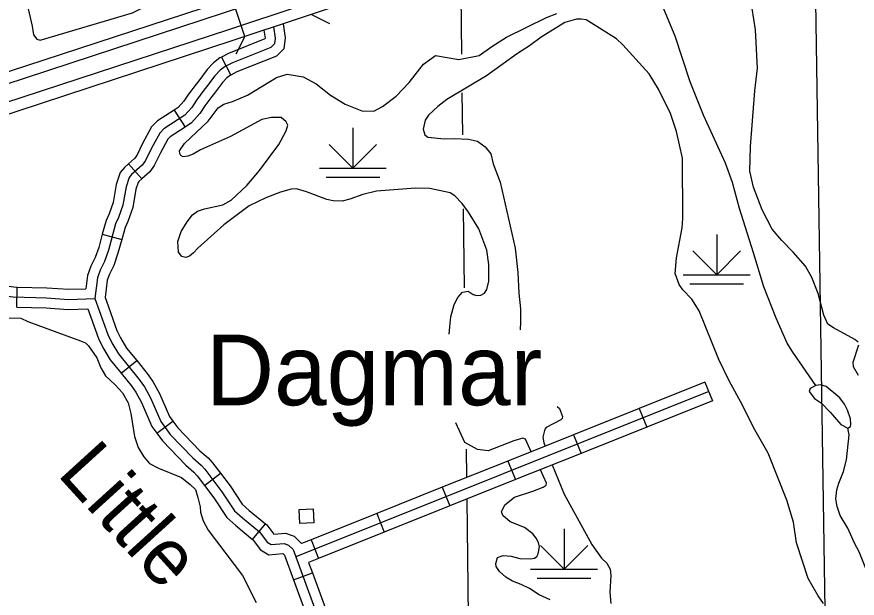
# Model space of a CAD drawing. Extents: x 1084508 to 1142749, y 1057638 to 1093403.
# Drawn here: x 1091747 to 1093716, y 1070432 to 1071794 of the extents above; entities that cross this region are included whole.
import ezdxf

# ---------------------------------------------------------------- set-up
doc = ezdxf.new("R2010")
doc.units = 0
for name, color, linetype in [('Level 19', 7, 'Continuous'), ('Level 25', 7, 'Continuous'), ('Level 32', 7, 'Continuous'), ('Level 35', 7, 'Continuous'), ('Level 39', 7, 'Continuous'), ('Level 44', 7, 'Continuous'), ('Level 47', 7, 'Continuous'), ('Level 5', 7, 'Continuous'), ('Level 56', 7, 'Continuous'), ('Level 7', 7, 'Continuous')]:
    doc.layers.add(name, color=color, linetype=linetype)

msp = doc.modelspace()

# ---------------------------------------------------------------- linework, layer by layer
at = {"layer": 'Level 19'}
for points in [[(1086828.8, 1069564.8), (1086958.3, 1069597.9), (1087305.2, 1069683.8), (1087445.9, 1069710.7), (1087821, 1069773.1), (1088253.5, 1069840.9), (1088436.6, 1069876.1), (1088626, 1069927.2), (1088752.5, 1069969), (1088851.8, 1070006.5), (1088959.6, 1070052.9), (1089051.3, 1070099.1), (1089145.7, 1070149.3), (1089264, 1070224), (1089345.2, 1070271.9), (1090501.3, 1071000.2), (1091111.9, 1071388.7), (1091276, 1071487.3), (1091344.3, 1071524.2), (1091404.7, 1071552.9), (1091443.8, 1071569.2), (1091605.2, 1071625.7), (1092224.5, 1071828.5), (1094022, 1072425.4)], [(1094030.9, 1072400.2), (1092232.9, 1071803.1), (1091613.8, 1071600.4), (1091453.4, 1071544.3), (1091415.6, 1071528.5), (1091356.3, 1071500.4), (1091289.2, 1071464.1), (1091126, 1071366), (1090515.6, 1070977.7), (1089359.1, 1070249.2), (1089277.9, 1070201.2), (1089159.1, 1070126.2), (1089063.6, 1070075.4), (1088970.9, 1070028.7), (1088861.8, 1069981.8), (1088761.4, 1069943.9), (1088633.7, 1069901.6), (1088442.6, 1069850.1), (1088258.1, 1069814.7), (1087825.3, 1069746.7), (1087450.6, 1069684.4), (1087310.9, 1069657.7), (1086964.9, 1069572), (1086833.1, 1069538.3)], [(1094044.5, 1072361.7), (1092245.7, 1071764.4), (1091626.8, 1071561.8), (1091468, 1071506.2), (1091432.2, 1071491.3), (1091374.8, 1071464), (1091309.5, 1071428.7), (1091147.4, 1071331.3), (1090537.4, 1070943.2), (1089380.4, 1070214.3), (1089299.2, 1070166.4), (1089179.6, 1070090.9), (1089082.3, 1070039.1), (1088988.1, 1069991.7), (1088877.1, 1069943.9), (1088775, 1069905.4), (1088645.4, 1069862.5), (1088451.8, 1069810.3), (1088265.1, 1069774.4), (1087831.8, 1069706.5), (1087457.7, 1069644.3), (1087319.6, 1069617.8), (1086974.8, 1069532.5), (1086844.1, 1069499)], [(1086853, 1069473.8), (1086981.3, 1069506.6), (1087325.3, 1069591.8), (1087462.4, 1069618), (1087836, 1069680.1), (1088269.7, 1069748.2), (1088457.8, 1069784.3), (1088653.1, 1069837), (1088783.9, 1069880.3), (1088887.1, 1069919.2), (1088999.4, 1069967.5), (1089094.6, 1070015.5), (1089193, 1070067.8), (1089313.1, 1070143.6), (1089394.3, 1070191.5), (1090551.7, 1070920.7), (1091161.5, 1071308.6), (1091322.7, 1071405.5), (1091386.9, 1071440.2), (1091443.1, 1071466.9), (1091477.6, 1071481.3), (1091635.4, 1071536.5), (1092254, 1071739), (1094053.4, 1072336.6)]]:
    msp.add_lwpolyline(points, dxfattribs=at)
at = {"layer": 'Level 32'}
for p, q in [((1092227.1, 1071699.4), (1092248.6, 1071657.5)), ((1092116.1, 1071575.2), (1092141.8, 1071535.7)), ((1092009.2, 1071449.5), (1092040.2, 1071414.1)), ((1091947.6, 1071284.5), (1091993, 1071272)), ((1091747.2, 1071113.6), (1091748.4, 1071160.7)), ((1091991.6, 1070958.9), (1092028.1, 1070988.7)), ((1093359.8, 1070937.8), (1093377.3, 1070894.1)), ((1093205.9, 1070876.2), (1093223.4, 1070832.5)), ((1092075.1, 1070818.3), (1092112.9, 1070846.3)), ((1093052, 1070814.6), (1093069.5, 1070770.9)), ((1092898.2, 1070753), (1092915.7, 1070709.3)), ((1092186.7, 1070696), (1092224.2, 1070724.4)), ((1092744.3, 1070691.4), (1092761.8, 1070647.7)), ((1092590.5, 1070629.8), (1092608, 1070586.1)), ((1092299.8, 1070569.4), (1092329.8, 1070605.6)), ((1092436.6, 1070568.2), (1092454.1, 1070524.5)), ((1092395.8, 1070474.6), (1092440, 1070490.8))]:
    msp.add_line(p, q, dxfattribs=at)
for points in [[(1092371.2, 1071777.9), (1092376.4, 1071744.7), (1092373.3, 1071719.3), (1092355.6, 1071702.1), (1092262.8, 1071664.8), (1092248.6, 1071657.5)], [(1092348.6, 1071770.4), (1092352.6, 1071744.3), (1092351, 1071730.4), (1092342.5, 1071722.2), (1092253, 1071686.3), (1092235.8, 1071677.4), (1092223.9, 1071668.6), (1092211.5, 1071655.4), (1092192, 1071629.6)], [(1092325.9, 1071762.9), (1092328.9, 1071743.9), (1092328.6, 1071742), (1092243.2, 1071707.7), (1092227.1, 1071699.4)], [(1092227.1, 1071699.4), (1092223.3, 1071697.5), (1092208.2, 1071686.3), (1092193.4, 1071670.6), (1092173.4, 1071644), (1092167.2, 1071636.3), (1092149.2, 1071612.5), (1092138.4, 1071596.1), (1092125.4, 1071581.2), (1092116.1, 1071575.2)], [(1092248.6, 1071657.5), (1092248.2, 1071657.4), (1092239.6, 1071651), (1092229.5, 1071640.2), (1092210.6, 1071615.1), (1092204.3, 1071607.3), (1092187.7, 1071585.3), (1092176, 1071567.5), (1092156.5, 1071545.3), (1092141.8, 1071535.7)], [(1092192, 1071629.6), (1092185.8, 1071621.8), (1092168.4, 1071598.9), (1092157.2, 1071581.8), (1092141, 1071563.3), (1092092, 1071531.5), (1092082.1, 1071521.6), (1092062.8, 1071486.3), (1092048.5, 1071457.1), (1092041.1, 1071446.1), (1092016.2, 1071424.4), (1092010.3, 1071417.2), (1092003.3, 1071395.6), (1091995.8, 1071352.8), (1091985.7, 1071323.5), (1091978.7, 1071308.8), (1091961.7, 1071246.8), (1091953, 1071220.6), (1091942.5, 1071200.4), (1091936, 1071182.2), (1091930.3, 1071133.6)], [(1092116.1, 1071575.2), (1092077.2, 1071549.9), (1092063.1, 1071536), (1092041.8, 1071497.1), (1092028.1, 1071468.9), (1092023.3, 1071461.8), (1092009.2, 1071449.5)], [(1092141.8, 1071535.7), (1092106.9, 1071513), (1092101.1, 1071507.3), (1092083.7, 1071475.5), (1092069, 1071445.3), (1092058.9, 1071430.4), (1092040.2, 1071414.1)], [(1092009.2, 1071449.5), (1091999.4, 1071440.9), (1091989.3, 1071428.8), (1091980.3, 1071401.2), (1091972.9, 1071358.7), (1091963.8, 1071332.4), (1091956.6, 1071317), (1091947.6, 1071284.5)], [(1092040.2, 1071414.1), (1092033.1, 1071407.9), (1092031.2, 1071405.6), (1092026.2, 1071389.9), (1092018.7, 1071346.9), (1092007.5, 1071314.6), (1092000.9, 1071300.6), (1091993, 1071272)], [(1091947.6, 1071284.5), (1091939.1, 1071253.6), (1091931.2, 1071229.8), (1091920.8, 1071209.9), (1091912.9, 1071187.6), (1091909.3, 1071156.5)], [(1091993, 1071272), (1091984.2, 1071239.9), (1091974.7, 1071211.4), (1091964.1, 1071191), (1091959, 1071176.8), (1091954.3, 1071136.3), (1091957.3, 1071127.9)], [(1091235.4, 1071212.6), (1091275.6, 1071150.7), (1091294.6, 1071116.2), (1091309.1, 1071099.4), (1091324.3, 1071086.5), (1091336.7, 1071082.9), (1091349.8, 1071084.1), (1091360.3, 1071088.3), (1091371.6, 1071095.9), (1091394.6, 1071117.9), (1091427, 1071139.6), (1091440.8, 1071146.1), (1091459.1, 1071152.2), (1091492.2, 1071156), (1091521.7, 1071154), (1091551.7, 1071149.2), (1091587.5, 1071147.2), (1091659, 1071147.1), (1091738.6, 1071137.4), (1091816.8, 1071135.4), (1091868.3, 1071131.8), (1091930.3, 1071133.6)], [(1091584, 1071171), (1091588.2, 1071170.7), (1091660.4, 1071170.7), (1091740.4, 1071160.9), (1091748.4, 1071160.7)], [(1091748.4, 1071160.7), (1091817.9, 1071158.9), (1091868.8, 1071155.4), (1091909.3, 1071156.5)], [(1091930.3, 1071133.6), (1091960.2, 1071049.5), (1091969.7, 1071030.1), (1091985.2, 1071004), (1092034.2, 1070944), (1092046.1, 1070927.1), (1092060.6, 1070900.7), (1092084.4, 1070845.3), (1092106.5, 1070815.4), (1092159.8, 1070760.2), (1092178.9, 1070743.3), (1092187.7, 1070733.6), (1092227.7, 1070680.8), (1092257.7, 1070636.1), (1092276.2, 1070619.5), (1092315.7, 1070586.8), (1092333.8, 1070563), (1092343.5, 1070557.4), (1092373.8, 1070559.8), (1092384.2, 1070556.1), (1092395, 1070545.5), (1092575.9, 1070049.5)], [(1091957.3, 1071127.9), (1091981.9, 1071058.7), (1091990.5, 1071041.3), (1092004.5, 1071017.5), (1092028.1, 1070988.7)], [(1091747.2, 1071113.6), (1091815.6, 1071111.9), (1091867.8, 1071108.2), (1091913.9, 1071109.6)], [(1091913.9, 1071109.6), (1091938.5, 1071040.4), (1091949, 1071018.9), (1091965.8, 1070990.5), (1091991.6, 1070958.9)], [(1092028.1, 1070988.7), (1092052.9, 1070958.2), (1092066.1, 1070939.6), (1092081.8, 1070911), (1092104.9, 1070857.1), (1092112.9, 1070846.3)], [(1091991.6, 1070958.9), (1092015.4, 1070929.7), (1092026.1, 1070914.6), (1092039.4, 1070890.3), (1092063.8, 1070833.5), (1092075.1, 1070818.3)], [(1093359.8, 1070937.8), (1093205.9, 1070876.2)], [(1093368.5, 1070915.9), (1092400.8, 1070528.6)], [(1093377.3, 1070894.1), (1093223.4, 1070832.5)], [(1093205.9, 1070876.2), (1093052, 1070814.6)], [(1092112.9, 1070846.3), (1092124.5, 1070830.6), (1092176, 1070777.2), (1092195.4, 1070760.2), (1092205.9, 1070748.7), (1092224.2, 1070724.4)], [(1093223.4, 1070832.5), (1093069.5, 1070770.9)], [(1092075.1, 1070818.3), (1092088.5, 1070800.1), (1092143.5, 1070743.2), (1092162.4, 1070726.5), (1092169.6, 1070718.6), (1092186.7, 1070696)], [(1093052, 1070814.6), (1092898.2, 1070753)], [(1093069.5, 1070770.9), (1092915.7, 1070709.3)], [(1092898.2, 1070753), (1092744.3, 1070691.4)], [(1092224.2, 1070724.4), (1092246.9, 1070694.5), (1092275.6, 1070651.6), (1092291.5, 1070637.3), (1092329.8, 1070605.6)], [(1092186.7, 1070696), (1092208.5, 1070667.1), (1092239.7, 1070620.5), (1092260.8, 1070601.7), (1092299.8, 1070569.4)], [(1092915.7, 1070709.3), (1092761.8, 1070647.7)], [(1092744.3, 1070691.4), (1092590.5, 1070629.8)], [(1092761.8, 1070647.7), (1092608, 1070586.1)], [(1092590.5, 1070629.8), (1092436.6, 1070568.2)], [(1092329.8, 1070605.6), (1092332.8, 1070603.2), (1092349.3, 1070581.4), (1092376.8, 1070583.7), (1092397, 1070576.6), (1092414.5, 1070559.4)], [(1092608, 1070586.1), (1092454.1, 1070524.5)], [(1092298.6, 1070570.4), (1092317.9, 1070545), (1092338, 1070533.3), (1092370.7, 1070535.9), (1092371.5, 1070535.7), (1092374.7, 1070532.5), (1092395.8, 1070474.6)], [(1092436.6, 1070568.2), (1092414.5, 1070559.4)], [(1092454.1, 1070524.5), (1092431.1, 1070515.3)], [(1092431.1, 1070515.3), (1092440, 1070490.8)], [(1092440, 1070490.8), (1092496.8, 1070335.1)], [(1092395.8, 1070474.6), (1092452.6, 1070318.9)]]:
    msp.add_lwpolyline(points, dxfattribs=at)
at = {"layer": 'Level 35'}
for points in [[(1091985.3, 1072060.6), (1091977, 1072077), (1091971.5, 1072080.9), (1091957.1, 1072081.7), (1091827.3, 1072034.7), (1091798.4, 1072026.5), (1091763.8, 1072021.9), (1091751.4, 1072016.5), (1091746, 1072010), (1091742.1, 1071995.4), (1091740.5, 1071974), (1091744.8, 1071938.3), (1091783.1, 1071772.3), (1091786.5, 1071751.6), (1091794.1, 1071741.8), (1091802.3, 1071739.6), (1092018, 1071803.5), (1092043, 1071816), (1092052.2, 1071823.8), (1092053.6, 1071837.1), (1092050.8, 1071855.9)], [(1093619.5, 1070930.3), (1093565.3, 1071007.8), (1093552.4, 1071029.1), (1093526.7, 1071087.7), (1093497.4, 1071160.9), (1093473.5, 1071240.9), (1093440.7, 1071344.6), (1093424.4, 1071405.6), (1093407.5, 1071451.3), (1093356.6, 1071563.8), (1093325, 1071641.4), (1093290.2, 1071748.4), (1093252.8, 1071839.3), (1093239.1, 1071856.7), (1093218.5, 1071874.3), (1093196.1, 1071887.1), (1093150.4, 1071906.4), (1093118.4, 1071925.1), (1093101.5, 1071945.6), (1093077.3, 1071997), (1093072.3, 1072010.8)], [(1091668.9, 1071064.8), (1091694.9, 1071079.6), (1091726, 1071088.5), (1091756.7, 1071087.6), (1091773.2, 1071080.3), (1091896.6, 1071035), (1091908.1, 1071029.7), (1091915.2, 1071023), (1091934.6, 1070995), (1091944.4, 1070971.5), (1091954.7, 1070952.6), (1091977.6, 1070931.4), (1091994.8, 1070913.1), (1092008.1, 1070889.6), (1092014.6, 1070864.7), (1092022.8, 1070810.7)], [(1093694.2, 1070830), (1093700.6, 1070833.6), (1093701.7, 1070839.6), (1093700.4, 1070851.6), (1093693.5, 1070871.8), (1093686.7, 1070886.3), (1093675.9, 1070900.7), (1093643.4, 1070927.3), (1093630.7, 1070931.6), (1093619.5, 1070930.3), (1093606.3, 1070923), (1093603.7, 1070915.7), (1093616.4, 1070899.7), (1093633.1, 1070888.3), (1093653.5, 1070867.6), (1093678.2, 1070838.2), (1093694.2, 1070830)], [(1093882.6, 1070173.3), (1093855.7, 1070200.1), (1093834.3, 1070234), (1093808.9, 1070282.9), (1093795.1, 1070312.3), (1093764.7, 1070399.9), (1093754.1, 1070447.7), (1093744.9, 1070481.4), (1093721.3, 1070540.3), (1093710, 1070560.4), (1093694.2, 1070595.7), (1093676.6, 1070625.3), (1093669.4, 1070646.5), (1093666.6, 1070664.3), (1093668.4, 1070685.1), (1093673.2, 1070701.3), (1093684.3, 1070728.7), (1093691.8, 1070756), (1093697.5, 1070814.4), (1093694.2, 1070830)], [(1092022.8, 1070810.7), (1092031.2, 1070784.3), (1092044.5, 1070763), (1092058.2, 1070747.4), (1092079.3, 1070735.9), (1092133.2, 1070714.1), (1092153.5, 1070698.1), (1092165.8, 1070685.9), (1092171.7, 1070667.5), (1092176.5, 1070646), (1092177.8, 1070632.8), (1092183.5, 1070612.6), (1092195.8, 1070591.3), (1092276, 1070484.8), (1092308.1, 1070421.7)]]:
    msp.add_lwpolyline(points, dxfattribs=at)
at = {"layer": 'Level 39'}
for p, q in [((1092281.5, 1071748.1), (1092251.9, 1071837.5)), ((1092437.7, 1071799.6), (1092479.8, 1071778.5)), ((1092281.5, 1071748.1), (1092260.4, 1071706.1))]:
    msp.add_line(p, q, dxfattribs=at)
at = {"layer": 'Level 44'}
for p, q in [((1092534.7, 1071533.6), (1092534.7, 1071439.4)), ((1092534.7, 1071439.4), (1092479.2, 1071494.9)), ((1092534.7, 1071439.4), (1092590.2, 1071494.9)), ((1092456.2, 1071439.4), (1092613.1, 1071439.4)), ((1092471.9, 1071418), (1092597.5, 1071418)), ((1093387.2, 1071283.9), (1093387.2, 1071189.7)), ((1093387.2, 1071189.7), (1093331.7, 1071245.2)), ((1093387.2, 1071189.7), (1093442.7, 1071245.2)), ((1093308.7, 1071189.7), (1093465.6, 1071189.7)), ((1093324.4, 1071168.3), (1093449.9, 1071168.3)), ((1093029.5, 1070593.7), (1093029.5, 1070499.5)), ((1093029.5, 1070499.5), (1092974, 1070555)), ((1093029.5, 1070499.5), (1093084.9, 1070555)), ((1092951, 1070499.5), (1093107.9, 1070499.5)), ((1092966.7, 1070478.2), (1093092.2, 1070478.2))]:
    msp.add_line(p, q, dxfattribs=at)
at = {"layer": 'Level 47'}
for points in [[(1092291.7, 1071350.8), (1092232.2, 1071306.6), (1092171.1, 1071252.2), (1092161.5, 1071240.5), (1092151.5, 1071233.4), (1092143.2, 1071229.6), (1092133.7, 1071232.1), (1092125.8, 1071242.1), (1092124.4, 1071267.6), (1092132, 1071290.5), (1092146.4, 1071313.7), (1092159.2, 1071330.3), (1092170.4, 1071338.6), (1092186.8, 1071344.3), (1092230.3, 1071353), (1092249.6, 1071364.2), (1092286.1, 1071398.7), (1092316.2, 1071434.2), (1092361.1, 1071494.9), (1092378, 1071526.7), (1092382.1, 1071539.8), (1092378.7, 1071547.5), (1092367, 1071558), (1092344.4, 1071558.1), (1092321.1, 1071553), (1092247.9, 1071513.5), (1092177.8, 1071482), (1092160.6, 1071471.9), (1092147.7, 1071467.3), (1092137.1, 1071465.9), (1092131.3, 1071468.8), (1092128.9, 1071473.4), (1092128.7, 1071480), (1092140.2, 1071497.2), (1092195.4, 1071549.4), (1092219.2, 1071580.6), (1092232, 1071589), (1092252.7, 1071595.2), (1092287.5, 1071610.5), (1092355.4, 1071651.9), (1092380.7, 1071659.3), (1092418.2, 1071653.6), (1092449, 1071636.6), (1092482.6, 1071610.6), (1092517, 1071589.3), (1092555.5, 1071573.6), (1092583.7, 1071572.6), (1092604, 1071583.8), (1092636.5, 1071608.1), (1092666.5, 1071639.8), (1092700.5, 1071683.4), (1092728.5, 1071703.1), (1092783, 1071694.3), (1092830.9, 1071703.5), (1092860.4, 1071724.8), (1092894.3, 1071746.3), (1092988.8, 1071792.7), (1093012.9, 1071801.5)], [(1093719, 1071031.7), (1093711.3, 1071038), (1093660.9, 1071065), (1093647.5, 1071074), (1093638, 1071095.1), (1093625.1, 1071145.9), (1093609.8, 1071183.1), (1093595.2, 1071210), (1093566.5, 1071242.7), (1093540, 1071270.1), (1093517.5, 1071296.4), (1093493.8, 1071341.9), (1093473.6, 1071394.7), (1093465.2, 1071432.5), (1093466.5, 1071490.3), (1093476.7, 1071620.2), (1093482.8, 1071673.6), (1093478.1, 1071763.3), (1093470.2, 1071813.7)], [(1093081.1, 1071786.6), (1093069.8, 1071788.4), (1093058.9, 1071788.3), (1093031.3, 1071780.9), (1092975.7, 1071746.5), (1092948.7, 1071725.6), (1092920.6, 1071708.1), (1092847.8, 1071655.7), (1092754.9, 1071600), (1092733.9, 1071583.5), (1092711.9, 1071563.4), (1092703.9, 1071551.7), (1092699.1, 1071530.8), (1092703.4, 1071517.7), (1092710.5, 1071512), (1092748.6, 1071507.9), (1092772, 1071508.9), (1092805.6, 1071507.4), (1092826.5, 1071502.6), (1092844.5, 1071489.2), (1092857.7, 1071472.8), (1092863.4, 1071449.7), (1092880.1, 1071406.4), (1092914.9, 1071251.8), (1092921.3, 1071194.8), (1092923.9, 1071146.2), (1092927.5, 1071109.9), (1092927.6, 1071078.1), (1092926.6, 1071060.6)], [(1093637.5, 1070419.4), (1093624.7, 1070436.9), (1093601.4, 1070477.6), (1093574.3, 1070561.3), (1093567.1, 1070609.8), (1093551.7, 1070661.5), (1093508, 1070771.7), (1093473.2, 1070831.5), (1093447.4, 1070884.1), (1093416.7, 1070940.7), (1093392.2, 1070991.1), (1093346.3, 1071104.7), (1093328.8, 1071132.1), (1093307.7, 1071154.1), (1093299.2, 1071167), (1093289.9, 1071192.1), (1093293.1, 1071229.4), (1093306.2, 1071299.3), (1093308, 1071321.7), (1093307.5, 1071462.8), (1093293.3, 1071525.5), (1093279.1, 1071567.5), (1093250.6, 1071624.1), (1093228.8, 1071660.5), (1093167.1, 1071728.6), (1093152.2, 1071742.3), (1093081.1, 1071786.6)], [(1092760.2, 1071050.3), (1092761.7, 1071067.5), (1092764.5, 1071091.2), (1092772.1, 1071119.8), (1092780.9, 1071135.9), (1092791.3, 1071148.9), (1092804.7, 1071150.7), (1092816.6, 1071143.4), (1092825.1, 1071140.6), (1092834.2, 1071141.3), (1092843.4, 1071146.4), (1092848.4, 1071154.7), (1092853.5, 1071174.4), (1092853.5, 1071213.8), (1092848.4, 1071247.5), (1092830.1, 1071297.1), (1092805.3, 1071336), (1092791, 1071356.5), (1092774, 1071374.1), (1092762.8, 1071381.5), (1092714.8, 1071391.8), (1092681.5, 1071392.6), (1092590, 1071385.7), (1092558.1, 1071377.8), (1092527.2, 1071366.8), (1092509.3, 1071362.3), (1092488.9, 1071362.4), (1092473.4, 1071365.8), (1092426, 1071384), (1092402.3, 1071390.6), (1092390.1, 1071390.1), (1092365, 1071383.4), (1092330.8, 1071369.7), (1092291.7, 1071350.8)], [(1093719.4, 1070953.1), (1093707.7, 1070974.1), (1093706.8, 1070984.8), (1093720.2, 1071025.4)], [(1093013.3, 1070880.6), (1093018.5, 1070875.9), (1093026.1, 1070857.3), (1093025.1, 1070852.5), (1093021.8, 1070849.6), (1092987.7, 1070831.2), (1092984.4, 1070827.6), (1092979.9, 1070809.2), (1092982.3, 1070795.7), (1092985.5, 1070788)], [(1092797.2, 1070796.7), (1092775.8, 1070842.6)], [(1092952.8, 1070774.9), (1092939.2, 1070804.5), (1092932.6, 1070806.7), (1092912.2, 1070800.6), (1092852.1, 1070776.7), (1092826.6, 1070780.1), (1092797.2, 1070796.7)], [(1093001.7, 1070743.7), (1093029.7, 1070675.6), (1093094.6, 1070557.2), (1093117.2, 1070525.7), (1093129.9, 1070513.3), (1093137.3, 1070499.5), (1093139.5, 1070484.5), (1093137, 1070446), (1093139, 1070419)], [(1092956.5, 1070682.2), (1092981, 1070691.4), (1092988, 1070696.4), (1092988.5, 1070701.2), (1092974.1, 1070732.7)], [(1092903.6, 1070610.7), (1092885.8, 1070625.2), (1092883.3, 1070634.2), (1092890.7, 1070650.6), (1092913.2, 1070668.2), (1092956.5, 1070682.2)], [(1092997.1, 1070428), (1092971.6, 1070439.2), (1092948.7, 1070454.3), (1092928.9, 1070463.9), (1092908.6, 1070471.5), (1092893.2, 1070481), (1092878.2, 1070493.9), (1092870.6, 1070505.5), (1092869.6, 1070512.7), (1092873.8, 1070527), (1092886.7, 1070531.7), (1092905.9, 1070529.9), (1092926.2, 1070524.8), (1092951.6, 1070523.9), (1092960, 1070525.2), (1092966, 1070529.6), (1092968.9, 1070535.7), (1092971.7, 1070551.5), (1092969.8, 1070561.8), (1092964.3, 1070572.3), (1092956.1, 1070582.3), (1092936.7, 1070597.2), (1092903.6, 1070610.7)]]:
    msp.add_lwpolyline(points, dxfattribs=at)
at = {"layer": 'Level 5'}
for points in [[(1092786.6, 1071915.9), (1092789.1, 1071706.6)], [(1092790.2, 1071615.9), (1092791.3, 1071517.1)], [(1092793.4, 1071344.2), (1092795.6, 1071158.7)], [(1092800.2, 1070780.5), (1092801, 1070714.1)], [(1092801.6, 1070663.6), (1092804.9, 1070389.3), (1092838.6, 1069154.3)]]:
    msp.add_lwpolyline(points, dxfattribs=at)
at = {"layer": 'Level 56'}
msp.add_lwpolyline([(1092410.4, 1070606.7), (1092409.1, 1070639.3), (1092441.9, 1070640.6), (1092443.1, 1070608)], close=True, dxfattribs=at)
at = {"layer": 'Level 7'}
msp.add_lwpolyline([(1093614.8, 1072085.4), (1093641, 1070404.5)], dxfattribs=at)

# ---------------------------------------------------------------- texts
at = {"layer": 'Level 25'}
msp.add_text('Dagmar', height=165.73, dxfattribs=at).set_placement((1092190, 1070883.7))
at = {"layer": 'Level 35'}
msp.add_text('Little', height=132.58, rotation=312.2826, dxfattribs=at).set_placement((1091839.2, 1070722.1))

doc.saveas('drawing.dxf')
